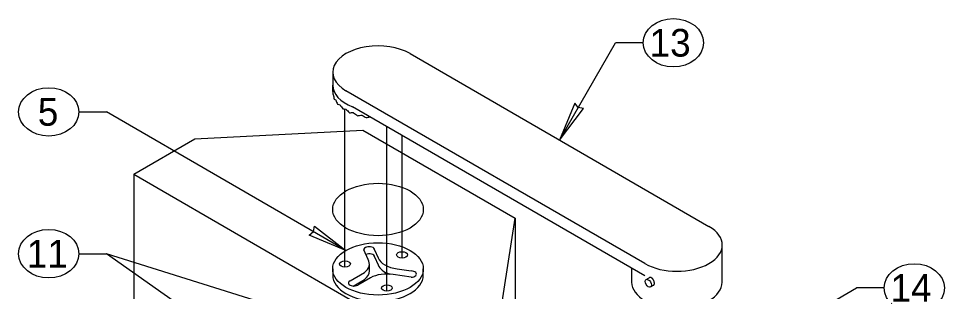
# Model space of a CAD drawing. Extents: x 99862 to 104211, y 98939 to 105076.
# Drawn here: x 100780 to 101317, y 100554 to 100711 of the extents above; entities that cross this region are included whole.
import ezdxf

# ---------------------------------------------------------------- set-up
doc = ezdxf.new("R2010")
doc.units = 0
for name, color, linetype in [('Level 11', 7, 'Continuous'), ('Level 13', 7, 'Continuous'), ('Level 15', 7, 'Continuous'), ('Level 16', 7, 'Continuous'), ('Level 20', 7, 'Continuous'), ('Level 26', 7, 'Continuous'), ('Level 6', 7, 'Continuous')]:
    doc.layers.add(name, color=color, linetype=linetype)

msp = doc.modelspace()

# ---------------------------------------------------------------- linework, layer by layer
at = {"layer": 'Level 11'}
for p, q in [((100982.75, 100572.17), (100980.19, 100577.68)), ((100986.48, 100577.68), (100988.62, 100573.07)), ((100986.48, 100573.57), (100988.62, 100568.97)), ((100983.47, 100565.49), (100983.47, 100569.6)), ((100962.21, 100566.64), (100962.21, 100563.07)), ((100972.23, 100559.84), (100980.59, 100564.66)), ((101007.59, 100561.86), (100997.21, 100563.41)), ((100999.61, 100566.73), (101007.59, 100565.49)), ((101014.71, 100563.07), (101014.71, 100566.64)), ((100974.01, 100556.76), (100980.59, 100560.56)), ((100984.08, 100561.54), (100976.68, 100557.27))]:
    msp.add_line(p, q, dxfattribs=at)
for centre, major_axis in [((100988.46, 100566.64), (26.25, 0)), ((101002.38, 100574.77), (3.14, 0)), ((100969.3, 100569.53), (3.14, 0)), ((100993.58, 100555.59), (3.14, 0))]:
    msp.add_ellipse(centre, major_axis=major_axis, ratio=0.57735, dxfattribs=at)
for centre, major_axis, start_param, end_param in [((100983.34, 100577.68), (3.14, 0), 0, 3.141593), ((100983.34, 100573.57), (3.14, 0), 0, 2.2227), ((101002.46, 100574.72), (14.14, 0), 3.345037, 4.508944), ((100969.33, 100569.6), (14.14, 0), 5.634137, 6.603339), ((101002.46, 100570.61), (14.14, 0), 3.345037, 4.166798), ((100988.46, 100563.07), (26.25, 0), 3.141593, 6.283185), ((100969.33, 100565.49), (14.14, 0), 5.634137, 6.283185), ((100993.59, 100555.59), (14.02, 0), 1.308997, 2.31608), ((101007.59, 100563.68), (3.14, 0), 4.712389, 7.853982), ((100974.46, 100558.55), (3.14, 0), 2.356194, 5.497787)]:
    msp.add_ellipse(centre, major_axis=major_axis, ratio=0.57735, start_param=start_param, end_param=end_param, dxfattribs=at)
at = {"layer": 'Level 13'}
for p, q in [((101007.02, 100691.18), (101180.26, 100591.16)), ((100962.21, 100680.46), (100962.21, 100672.93)), ((100962.2, 100669.3), (100962.2, 100672.93)), ((101143.14, 100569.72), (100969.9, 100669.75)), ((101143.14, 100562.58), (100973.72, 100660.39)), ((101187.95, 100559.01), (101187.95, 100580.44)), ((101135.45, 100567.02), (101135.45, 100559.01))]:
    msp.add_line(p, q, dxfattribs=at)
for centre, major_axis, ratio, start_param, end_param in [((100988.46, 100680.46), (26.25, 0), 0.57735, 0.785398, 3.926991), ((100988.46, 100672.93), (-26.25, 0), 0.57735, 0, 0.974759), ((100988.46, 100669.81), (-25.81, -5.13), 0.947565, 6.097095, 6.149455), ((100988.46, 100669.81), (-26.26, -1.61), 0.206802, 0.039705, 0.144424), ((100988.46, 100669.81), (24.15, -11.18), 0.922162, 3.702024, 3.806744), ((100988.46, 100669.81), (-26.25, -3.71), 0.223561, 0.230203, 0.327994), ((100988.46, 100669.81), (23.03, -14.79), 0.853385, 4.009326, 4.114045), ((100988.46, 100669.81), (-26.22, -5.73), 0.252109, 0.416228, 0.514019), ((100988.46, 100669.81), (23.21, -15.69), 0.783391, 4.204501, 4.308875), ((100988.46, 100669.81), (-26.17, -7.58), 0.292084, 0.595944, 0.694035), ((100988.46, 100669.81), (23.74, -15.68), 0.716006, 4.368664, 4.47373), ((100988.46, 100669.81), (-26.07, -9.36), 0.335596, 0.770561, 0.874936), ((100988.46, 100669.81), (24.25, -15.49), 0.650745, 4.537305, 4.635096), ((100988.46, 100669.81), (-25.92, -10.93), 0.386234, 0.938087, 1.042807), ((100988.46, 100669.81), (24.76, -14.88), 0.588004, 4.692487, 4.790278), ((100988.46, 100669.81), (-25.69, -12.32), 0.440657, 1.100807, 1.179316), ((101161.7, 100580.44), (26.25, 0), 0.57735, 3.926991, 7.068583), ((101161.7, 100559.01), (26.25, 0), 0.57735, 3.141593, 6.283185)]:
    msp.add_ellipse(centre, major_axis=major_axis, ratio=ratio, start_param=start_param, end_param=end_param, dxfattribs=at)
at = {"layer": 'Level 15'}
for p, q in [((101093.64, 100641.17), (101126.14, 100697.46)), ((101142.14, 100697.46), (101126.14, 100697.46)), ((100969.3, 100567.71), (100969.3, 100659.13)), ((100815.11, 100657.48), (100831.11, 100657.48)), ((100969.9, 100577.35), (100831.11, 100657.48)), ((100993.58, 100553.78), (100993.58, 100648.93)), ((101002.38, 100572.96), (101002.38, 100643.85)), ((100815.11, 100575.45), (100831.11, 100575.45)), ((100967.14, 100479.81), (100831.11, 100575.45)), ((100962.76, 100534.27), (100831.11, 100575.45)), ((101183.58, 100508.19), (101265.76, 100555.63)), ((101281.76, 100555.63), (101265.76, 100555.63))]:
    msp.add_line(p, q, dxfattribs=at)
for points in [[(101093.64, 100641.17), (101107.64, 100659.45), (101104.53, 100660.02), (101102.47, 100662.43)], [(100969.9, 100577.35), (100948.64, 100586.18), (100951.04, 100588.24), (100951.62, 100591.35)]]:
    msp.add_lwpolyline(points, close=True, dxfattribs=at)
at = {"layer": 'Level 16'}
for p, q in [((101143.85, 100560.53), (101145.67, 100561.58)), ((101146.35, 100556.2), (101148.17, 100557.25))]:
    msp.add_line(p, q, dxfattribs=at)
msp.add_ellipse((101145.1, 100558.37), major_axis=(1.25, -2.17), ratio=0.57735, dxfattribs=at)
at = {"layer": 'Level 20'}
for centre in [(101159.64, 100697.46), (100797.61, 100657.48), (100797.61, 100575.45), (101299.26, 100555.63)]:
    msp.add_ellipse(centre, major_axis=(-17.5, 0), ratio=0.8, dxfattribs=at)
at = {"layer": 'Level 26'}
for p, q in [((100882.39, 100641.84), (100979.62, 100646.94)), ((100979.62, 100646.94), (101068.01, 100595.91)), ((100847.04, 100621.43), (100882.39, 100641.84)), ((100847.04, 100621.43), (101023.82, 100519.36)), ((100847.04, 100621.43), (100847.04, 100512.28)), ((101059.17, 100539.78), (101068.01, 100595.91)), ((101068.01, 100595.91), (101068.01, 100371.79))]:
    msp.add_line(p, q, dxfattribs=at)
msp.add_ellipse((100988.46, 100601.01), major_axis=(26.25, 0), ratio=0.57735, dxfattribs=at)
at = {"layer": 'Level 6'}
for points in [[(101148.47, 100559.4), (101148.39, 100559.66), (101148.28, 100559.93), (101148.15, 100560.17), (101148.02, 100560.42), (101147.86, 100560.66), (101147.69, 100560.86), (101147.52, 100561.07), (101147.33, 100561.24), (101147.13, 100561.38), (101146.94, 100561.52), (101146.73, 100561.62), (101146.54, 100561.67), (101146.34, 100561.72), (101146.15, 100561.73), (101145.97, 100561.7), (101145.86, 100561.67), (101145.76, 100561.64), (101145.67, 100561.58)], [(101148.17, 100557.25), (101148.17, 100557.26), (101148.18, 100557.26), (101148.19, 100557.26), (101148.31, 100557.34), (101148.42, 100557.46), (101148.49, 100557.62), (101148.57, 100557.77), (101148.61, 100557.97), (101148.63, 100558.18), (101148.65, 100558.4), (101148.63, 100558.64), (101148.59, 100558.89), (101148.56, 100559.06), (101148.52, 100559.23), (101148.47, 100559.4)]]:
    msp.add_open_spline(points, degree=3, dxfattribs=at)

# ---------------------------------------------------------------- texts
at = {"layer": 'Level 20'}
for s, p in [('13', (101145.86, 100689.46)), ('5', (100791.3, 100649.48)), ('11', (100784.89, 100567.45)), ('14', (101285.48, 100547.63))]:
    msp.add_text(s, height=16, dxfattribs=at).set_placement(p)

doc.saveas('drawing.dxf')
